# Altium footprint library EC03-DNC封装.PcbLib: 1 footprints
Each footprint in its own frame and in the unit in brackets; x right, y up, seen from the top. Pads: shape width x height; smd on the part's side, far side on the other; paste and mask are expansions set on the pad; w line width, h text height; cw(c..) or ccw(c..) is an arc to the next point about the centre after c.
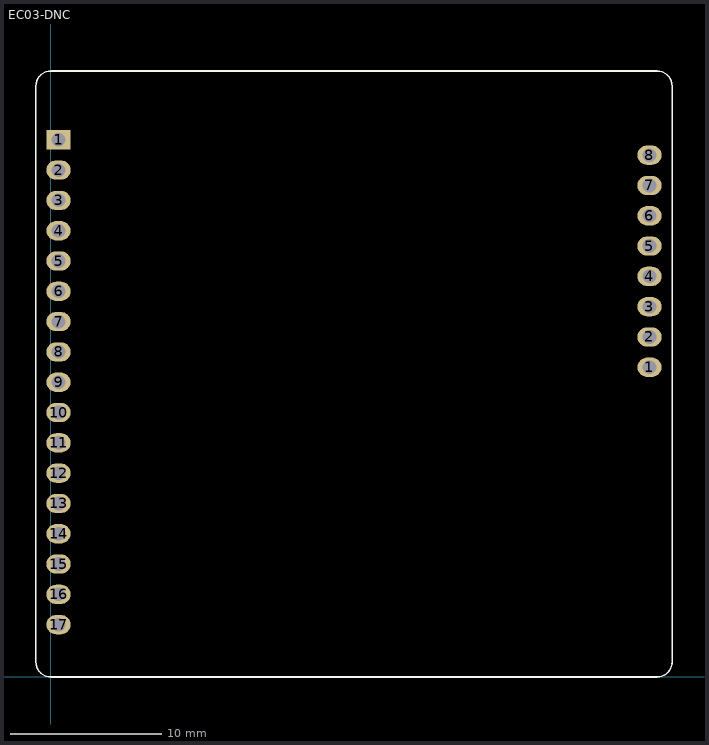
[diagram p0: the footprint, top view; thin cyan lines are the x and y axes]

## EC03-DNC [mm]
pads (25):
  rect 1.6x1.27 hole 0.9: 1(0.5,35.455)
  oval 1.6x1.27 hole 0.9: 1(39.5,20.442) 2(0.5,33.455) 2(39.5,22.442) 3(0.5,31.455) 3(39.5,24.442) 4(0.5,29.455) 4(39.5,26.442) 5(0.5,27.455) 5(39.5,28.442) 6(0.5,25.455) 6(39.5,30.442) 7(0.5,23.455) 7(39.5,32.442) 8(0.5,21.455) 8(39.5,34.442) 9(0.5,19.455) 10(0.5,17.455) 11(0.5,15.455) 12(0.5,13.455) 13(0.5,11.455) 14(0.5,9.455) 15(0.5,7.455) 16(0.5,5.455) 17(0.5,3.455)
Mid-Layer 2:
  lines w0.254: 0.351,20.991 0.928,20.991
Top Overlay:
  lines w0.1: -1,1 ccw(c0,1) 0,0 40,0 ccw(c40,1) 41,1 41,39 ccw(c40.002,38.998) 40,39.996 0,39.996 ccw(c-0.002,38.998) -1,39 -1,1
Bottom Overlay:
  lines w0.203: -0.719,34.439 1.719,34.439 ; 38.281,21.458 40.719,21.458 ; 40.694,35.712 38.281,35.712 38.281,19.198 40.719,19.198 40.719,35.712 ; -0.719,2.295 -0.719,36.7 1.719,36.7 1.719,2.295 -0.719,2.295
